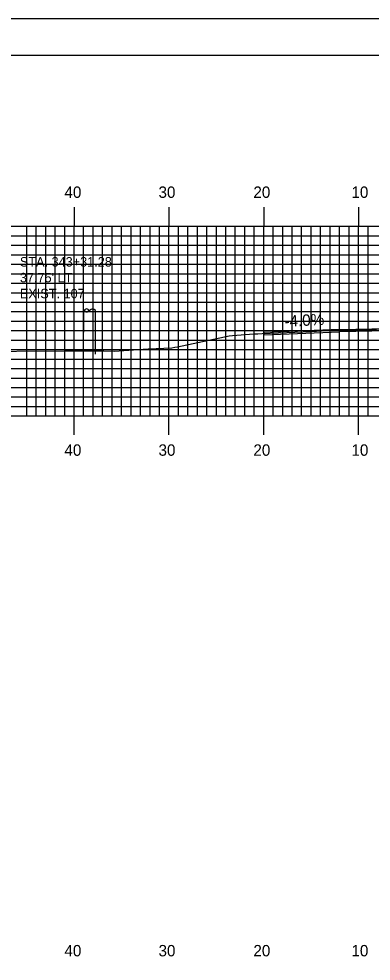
# Model space of a CAD drawing. Extents: x 1825147 to 1825490, y 442591 to 442811.
# Drawn here: x 1825266.5 to 1825303.7, y 442711.2 to 442810.5 of the extents above; entities that cross this region are included whole.
import ezdxf

# ---------------------------------------------------------------- set-up
doc = ezdxf.new("R2010")
doc.units = 0
for name, color, linetype in [('ANNOTATION', 7, 'Continuous'), ('BORDER', 7, 'Continuous'), ('D_Roadway_Edge_Shoulder', 7, 'Continuous'), ('D_Roadway_Edge_TW', 7, 'Continuous'), ('D_Text_Monospaced', 7, 'Continuous'), ('H_V ANNOTATION', 7, 'Continuous'), ('MAJOR', 7, 'Continuous'), ('MINOR', 7, 'Continuous'), ('PLOT BOUNDARY', 7, 'Continuous'), ('S_Roadway_Centerline', 7, 'Continuous'), ('S_Utilities_Pole_Power', 7, 'Continuous')]:
    doc.layers.add(name, color=color, linetype=linetype)

msp = doc.modelspace()

# ---------------------------------------------------------------- linework, layer by layer
at = {"layer": 'BORDER'}
msp.add_lwpolyline([(1825162.761, 442596.665), (1825482.761, 442596.665), (1825482.761, 442806.665), (1825162.761, 442806.665)], close=True, dxfattribs=at)
at = {"layer": 'D_Roadway_Edge_Shoulder'}
msp.add_lwpolyline([(1825300.361, 442777.783), (1825292.361, 442777.463), (1825292.361, 442777.213), (1825300.361, 442777.533)], close=True, dxfattribs=at)
at = {"layer": 'D_Roadway_Edge_TW'}
msp.add_lwpolyline([(1825300.361, 442777.533), (1825300.361, 442777.783), (1825312.361, 442778.023), (1825324.361, 442777.783), (1825324.361, 442777.533), (1825312.361, 442777.773)], close=True, dxfattribs=at)
at = {"layer": 'MAJOR'}
for p, q in [((1825272.361, 442790.669), (1825272.361, 442788.665)), ((1825282.361, 442790.669), (1825282.361, 442788.665)), ((1825292.361, 442790.669), (1825292.361, 442788.665)), ((1825302.361, 442790.669), (1825302.361, 442788.665)), ((1825172.361, 442788.665), (1825452.361, 442788.665)), ((1825172.361, 442788.665), (1825452.361, 442788.665)), ((1825272.361, 442768.665), (1825272.361, 442788.665)), ((1825282.361, 442768.665), (1825282.361, 442788.665)), ((1825292.361, 442768.665), (1825292.361, 442788.665)), ((1825302.361, 442768.665), (1825302.361, 442788.665)), ((1825172.361, 442783.665), (1825452.361, 442783.665)), ((1825172.361, 442778.665), (1825452.361, 442778.665)), ((1825172.361, 442773.665), (1825452.361, 442773.665)), ((1825172.361, 442768.665), (1825452.361, 442768.665)), ((1825172.361, 442768.665), (1825452.361, 442768.665)), ((1825272.361, 442766.661), (1825272.361, 442768.665)), ((1825282.361, 442766.661), (1825282.361, 442768.665)), ((1825292.361, 442766.661), (1825292.361, 442768.665)), ((1825302.361, 442766.661), (1825302.361, 442768.665))]:
    msp.add_line(p, q, dxfattribs=at)
at = {"layer": 'MINOR'}
for p, q in [((1825267.361, 442768.665), (1825267.361, 442788.665)), ((1825268.361, 442768.665), (1825268.361, 442788.665)), ((1825269.361, 442768.665), (1825269.361, 442788.665)), ((1825270.361, 442768.665), (1825270.361, 442788.665)), ((1825271.361, 442768.665), (1825271.361, 442788.665)), ((1825273.361, 442768.665), (1825273.361, 442788.665)), ((1825274.361, 442768.665), (1825274.361, 442788.665)), ((1825275.361, 442768.665), (1825275.361, 442788.665)), ((1825276.361, 442768.665), (1825276.361, 442788.665)), ((1825277.361, 442768.665), (1825277.361, 442788.665)), ((1825278.361, 442768.665), (1825278.361, 442788.665)), ((1825279.361, 442768.665), (1825279.361, 442788.665)), ((1825280.361, 442768.665), (1825280.361, 442788.665)), ((1825281.361, 442768.665), (1825281.361, 442788.665)), ((1825283.361, 442768.665), (1825283.361, 442788.665)), ((1825284.361, 442768.665), (1825284.361, 442788.665)), ((1825285.361, 442768.665), (1825285.361, 442788.665)), ((1825286.361, 442768.665), (1825286.361, 442788.665)), ((1825287.361, 442768.665), (1825287.361, 442788.665)), ((1825288.361, 442768.665), (1825288.361, 442788.665)), ((1825289.361, 442768.665), (1825289.361, 442788.665)), ((1825290.361, 442768.665), (1825290.361, 442788.665)), ((1825291.361, 442768.665), (1825291.361, 442788.665)), ((1825293.361, 442768.665), (1825293.361, 442788.665)), ((1825294.361, 442768.665), (1825294.361, 442788.665)), ((1825295.361, 442768.665), (1825295.361, 442788.665)), ((1825296.361, 442768.665), (1825296.361, 442788.665)), ((1825297.361, 442768.665), (1825297.361, 442788.665)), ((1825298.361, 442768.665), (1825298.361, 442788.665)), ((1825299.361, 442768.665), (1825299.361, 442788.665)), ((1825300.361, 442768.665), (1825300.361, 442788.665)), ((1825301.361, 442768.665), (1825301.361, 442788.665)), ((1825303.361, 442768.665), (1825303.361, 442788.665)), ((1825172.361, 442787.665), (1825452.361, 442787.665)), ((1825172.361, 442786.665), (1825452.361, 442786.665)), ((1825172.361, 442785.665), (1825452.361, 442785.665)), ((1825172.361, 442784.665), (1825452.361, 442784.665)), ((1825172.361, 442782.665), (1825452.361, 442782.665)), ((1825172.361, 442781.665), (1825452.361, 442781.665)), ((1825172.361, 442780.665), (1825452.361, 442780.665)), ((1825172.361, 442779.665), (1825452.361, 442779.665)), ((1825172.361, 442777.665), (1825452.361, 442777.665)), ((1825172.361, 442776.665), (1825452.361, 442776.665)), ((1825172.361, 442775.665), (1825452.361, 442775.665)), ((1825172.361, 442774.665), (1825452.361, 442774.665)), ((1825172.361, 442772.665), (1825452.361, 442772.665)), ((1825172.361, 442771.665), (1825452.361, 442771.665)), ((1825172.361, 442770.665), (1825452.361, 442770.665)), ((1825172.361, 442769.665), (1825452.361, 442769.665))]:
    msp.add_line(p, q, dxfattribs=at)
at = {"layer": 'PLOT BOUNDARY'}
msp.add_lwpolyline([(1825146.574, 442590.547), (1825486.574, 442590.547), (1825486.574, 442810.547), (1825146.574, 442810.547)], close=True, dxfattribs=at)
at = {"layer": 'S_Roadway_Centerline'}
msp.add_lwpolyline([(1825261.114, 442775.451), (1825271.443, 442775.535), (1825273.822, 442775.527), (1825275.488, 442775.548), (1825276.585, 442775.507), (1825280.179, 442775.754), (1825282.667, 442775.846), (1825282.991, 442775.925), (1825283.274, 442775.968), (1825288.726, 442777.113), (1825289.064, 442777.155), (1825291.325, 442777.313), (1825291.643, 442777.336), (1825291.662, 442777.337), (1825291.732, 442777.338), (1825292.196, 442777.343), (1825297.375, 442777.554), (1825299.017, 442777.679), (1825299.036, 442777.684), (1825299.11, 442777.683), (1825311.93, 442778.021)], dxfattribs=at)
at = {"layer": 'S_Utilities_Pole_Power'}
for p, q in [((1825273.36, 442779.794), (1825273.516, 442779.904)), ((1825273.36, 442775.175), (1825273.363, 442779.794)), ((1825273.516, 442779.683), (1825273.36, 442779.794)), ((1825273.828, 442779.904), (1825273.985, 442779.794)), ((1825273.985, 442779.794), (1825273.828, 442779.683)), ((1825274.141, 442779.904), (1825273.985, 442779.794)), ((1825274.61, 442779.794), (1825274.454, 442779.904)), ((1825274.61, 442775.175), (1825274.613, 442779.794))]:
    msp.add_line(p, q, dxfattribs=at)
for centre, start, end in [((1825273.672, 442779.684), 90, 125.26439), ((1825273.672, 442779.905), 234.73561, 270), ((1825273.672, 442779.684), 54.73561, 90), ((1825273.672, 442779.905), 270, 305.26439), ((1825274.297, 442779.684), 90, 125.26439), ((1825274.297, 442779.684), 54.73561, 90)]:
    msp.add_arc(centre, 0.271, start, end, dxfattribs=at)

# ---------------------------------------------------------------- texts
at = {"layer": 'ANNOTATION'}
msp.add_text('-4.0%', height=1.2, rotation=3.36949, dxfattribs=at).set_placement((1825294.587, 442778.036))
at = {"layer": 'D_Text_Monospaced'}
for s, height, p in [('STA. 343+31.28', 0.99996, (1825266.632, 442784.421)), ("37.75' LT.", 1, (1825266.632, 442782.753)), ('EXIST. 107', 1, (1825266.632, 442781.073))]:
    msp.add_text(s, height=height, dxfattribs=at).set_placement(p)
at = {"layer": 'H_V ANNOTATION'}
for s, p in [('40', (1825271.333, 442791.665)), ('30', (1825281.258, 442791.665)), ('20', (1825291.269, 442791.665)), ('10', (1825301.612, 442791.665)), ('40', (1825271.333, 442764.465)), ('30', (1825281.258, 442764.465)), ('20', (1825291.269, 442764.465)), ('10', (1825301.612, 442764.465)), ('40', (1825271.333, 442711.665)), ('30', (1825281.258, 442711.665)), ('20', (1825291.269, 442711.665)), ('10', (1825301.612, 442711.665))]:
    msp.add_text(s, height=1.2, dxfattribs=at).set_placement(p)

doc.saveas('drawing.dxf')
